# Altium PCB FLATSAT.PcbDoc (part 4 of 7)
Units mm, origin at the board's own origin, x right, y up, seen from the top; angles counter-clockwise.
Board outline 430 x 350 mm, 5 copper layers (Top Layer, Internal Plane 1, Internal Plane 2, DELETEME, Bottom Layer); 808 components, 852 nets, 6407 pads, 939 vias.
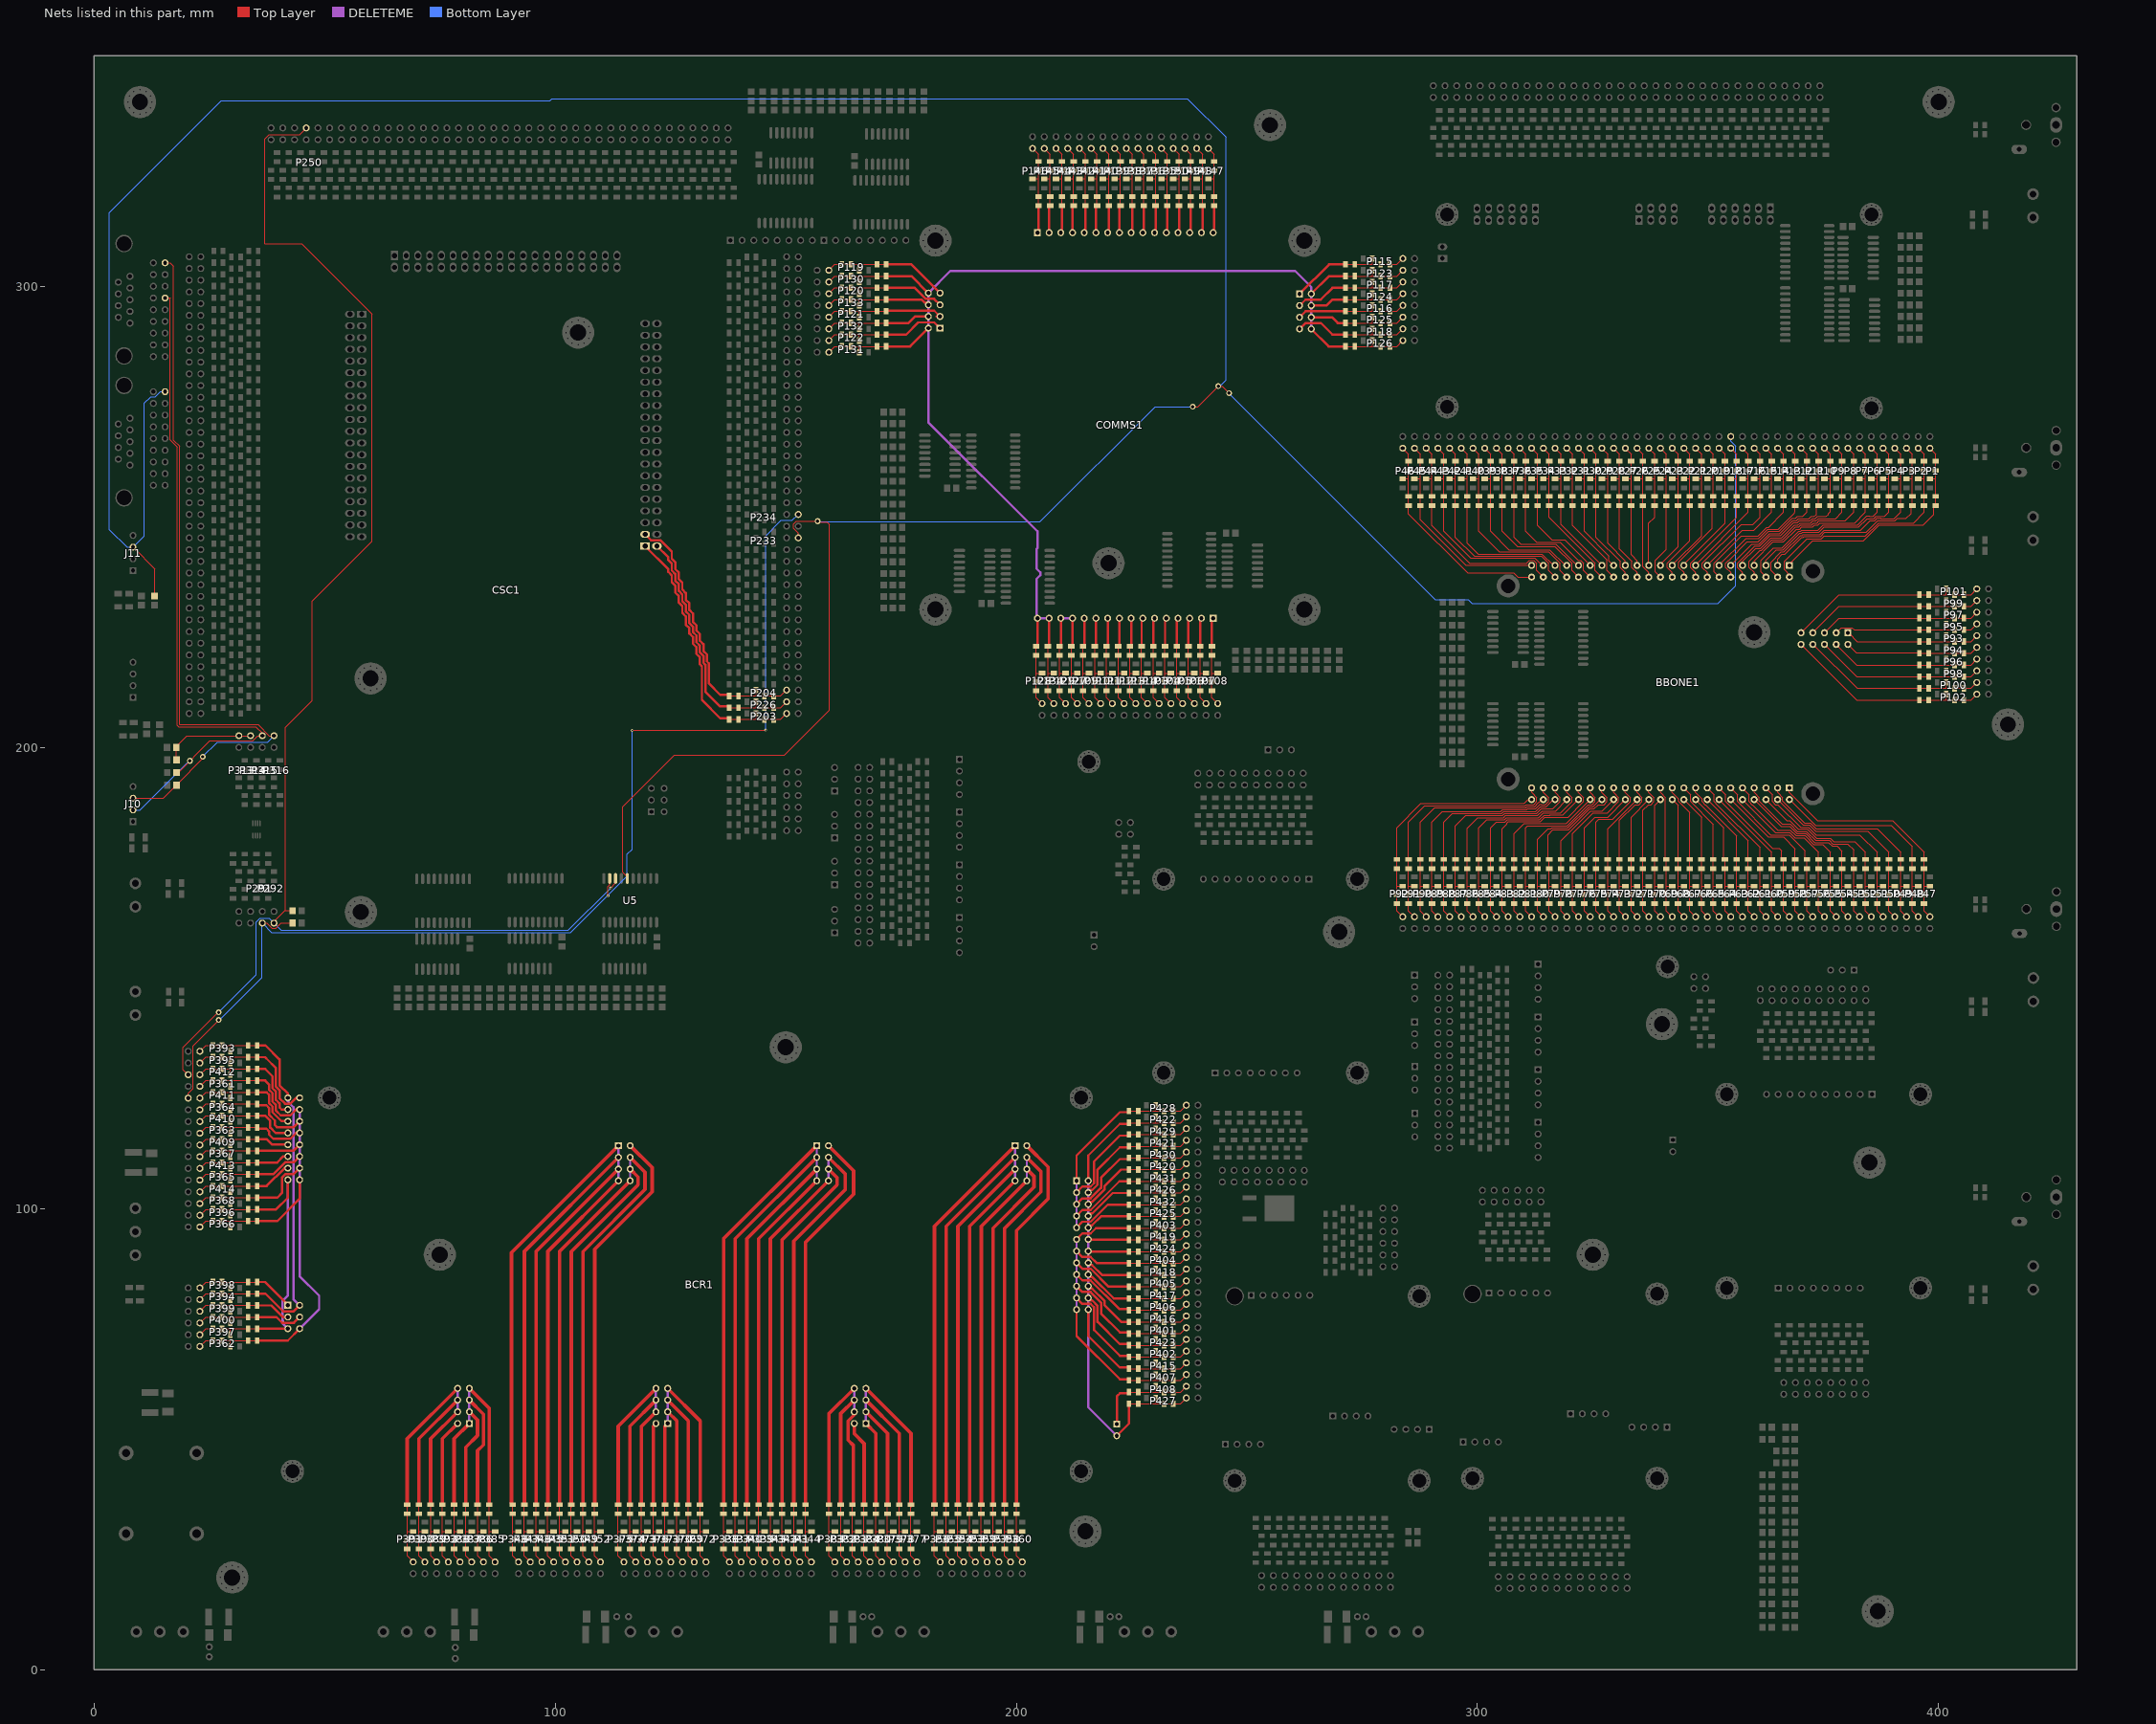
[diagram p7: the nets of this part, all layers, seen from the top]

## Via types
v1: diameter 1.016, hole 0.508, Top Layer to Bottom Layer, 541 vias
v2: diameter 0.6, hole 0.3, Top Layer to Bottom Layer, 214 vias
v3: diameter 1.27, hole 0.711, Top Layer to Bottom Layer, 147 vias
v4: diameter 0.8, hole 0.5, Top Layer to Bottom Layer, 31 vias
v5: diameter 0.5, hole 0.3, Top Layer to Bottom Layer, tented bottom, 5 vias
v6: diameter 1.27, hole 0.635, Top Layer to Bottom Layer, tented both sides, 1 vias

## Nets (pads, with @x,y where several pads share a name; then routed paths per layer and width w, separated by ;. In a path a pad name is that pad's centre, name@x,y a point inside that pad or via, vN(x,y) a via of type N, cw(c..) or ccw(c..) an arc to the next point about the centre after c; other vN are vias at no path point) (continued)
I2C1_SDA: J11.3 P18.1 P201.1 P233.1 R3.2 U5.6 | length 824.4
  Top Layer w0.152: U5.6@115.653,171.6 115.653,171.984 114.987,172.65 114.681,172.956 114.681,187.198 125.857,198.374 149.743,198.374 159.465,208.096 159.465,248.342 158.944,248.863 157.162,248.863 v3(156.925,249.1)
  Top Layer w0.254: J11.3@8.5,243.08 J11.3@8.5,243.46 13.233,238.727 R3.2@13.233,232.877 ; P233.1@152.734,245.474 152.734,246.522 151.679,247.577 151.679,248.451 152.328,249.1 v3(156.925,249.1) ; v3(238.252,273.914) 239.319,273.914 v3(243.789,278.384) 244.641,278.384 v3(246.15,276.875)
  Bottom Layer w0.254: P201.1@15.443,277.176 14.43,277.176 13.35,276.095 12.342,276.095 10.947,274.701 10.947,245.907 J11.3@8.5,243.46 7.163,243.46 3.404,247.219 3.404,316.027 27.661,340.284 98.874,340.284 99.313,340.723 237.077,340.723 245.44,332.359 245.44,279.679 244.145,278.384 v3(243.789,278.384) ; v3(156.925,249.1) 157.043,248.982 205.171,248.982 230.103,273.914 v3(238.252,273.914) ; v3(246.15,276.875) 245.9,277.125 245.8,277.125 290.82,232.105 298.001,232.105 298.855,231.25 352.164,231.25 356.01,235.096 356.01,265.34 354.918,266.433 P18.1@354.918,267.445
I2C2_SCL: P234.1 P291.1 P411.1 R8.2 U5.9 | length 254.4
  Top Layer w0.254: P411.1@20.451,123.96 20.451,124.973 21.531,126.053 21.531,135.323 26.935,140.727 26.935,141.224 27.051,141.108 27.247,141.108 v3(27.051,140.912) ; P291.1@36.519,161.92 37.532,161.92 38.612,160.84 39.507,160.84 40.591,161.925 R8.2@43.069,161.925 ; v2@111.435,167.869 111.435,169.796 111.917,170.278 111.917,171.526 U5.9@111.843,171.6 ; v2(111.481,167.869) v2@111.481,167.996 ; v2(116.713,203.708) 116.778,203.773 v2(145.669,203.773)
  Bottom Layer w0.254: v3(27.051,140.912) 27.247,141.108 27.443,141.108 36.42,150.085 P291.1@36.42,162.052 ; P291.1@36.519,161.92 38.547,159.893 103.378,159.893 112.074,168.589 115.646,172.161 115.646,176.84 116.713,177.907 v2(116.713,203.708) ; v2(145.669,203.773) 145.669,245.919 149,249.25 151.43,249.25 P234.1@152.734,250.554
I2C2_SCL_5V: J10.2 P191.1 P315.1 R10.2 | length 152
  Top Layer w0.254: P191.1@15.443,297.496 16.51,297.496 16.523,297.483 16.523,266.762 18.11,265.174 18.11,204.789 18.378,204.521 35.117,204.521 36.519,203.118 P315.1@36.519,202.56 35.507,202.56 34.427,201.48 25.188,201.48 R10.2@18.153,194.445
  Bottom Layer w0.254: J10.2@8.5,186.46 10.024,186.46 20.287,196.723 ; v3(20.812,197.104) v3@20.939,197.104
I2C2_SDA: P250.1 P292.1 P412.1 R7.2 U5.8 | length 329.6
  Top Layer w0.254: P412.1@20.451,129.04 19.371,130.121 19.371,135.009 26.826,142.465 26.935,142.465 v3(27.051,142.581) ; P292.1@39.059,161.92 39.059,162.3 41.529,164.77 41.529,204.35 47.371,210.192 47.371,231.775 60.325,244.729 60.325,293.99 45.07,309.245 37.084,309.245 37.084,332.012 37.987,332.914 44.594,332.914 P250.1@46.054,334.374 ; 41.368,164.592 R7.2@43.069,164.592 ; v2(112.039,169.545) 112.039,169.57 113.113,170.644 U5.8@113.113,171.6
  Bottom Layer w0.254: v3(27.051,142.581) 35.179,150.709 35.179,162.108 36.072,163.001 37.979,163.001 P292.1@39.059,161.92 40.579,160.401 102.87,160.401 v2@112.027,169.558 ; v2(112.039,169.545) v2@112.039,169.57
I2C2_SDA_5V: J10.3 P192.1 P316.1 R9.2 | length 159.8
  Top Layer w0.254: J10.3@8.5,189 15.075,189 R9.2@17.904,191.829 ; P192.1@15.443,305.116 16.51,305.116 17.272,304.354 17.272,266.659 18.567,265.364 18.567,204.978 35.629,204.978 38.047,202.56 P316.1@39.059,202.56 ; R9.2@17.562,192.187 18.187,192.187 v3@23.622,197.622
  Bottom Layer w0.254: v3(23.622,198) 26.79,201.168 37.667,201.168 P316.1@39.059,202.56
NetBBONE1_A01: BBONE1.A01 P1.2 | length 38.1
  Top Layer w0.254: BBONE1.A01@367.618,239.505 367.618,239.759 372.698,244.839 383.72,244.839 387.149,248.268 396.616,248.268 398.936,250.588 398.936,252.043 P1.2@399.368,252.475
NetBBONE1_A02: BBONE1.A02 P2.2 | length 40
  Top Layer w0.254: BBONE1.A02@367.618,236.965 367.618,237.514 366.526,238.606 366.526,240.404 371.418,245.296 374.599,245.296 375.157,245.855 384.09,245.855 386.96,248.725 394.534,248.725 396.828,251.02 P2.2@396.828,252.459
NetBBONE1_A03: BBONE1.A03 P3.2 | length 35.9
  Top Layer w0.254: BBONE1.A03@365.078,239.505 365.078,240.927 366.094,241.943 366.662,241.943 370.269,245.55 370.644,245.55 370.847,245.753 374.409,245.753 375.324,246.668 384.256,246.668 386.771,249.182 390.557,249.182 391.04,249.665 392.933,249.665 394.034,250.766 P3.2@394.034,252.221
NetBBONE1_A04: BBONE1.A04 P4.2 | length 37.9
  Top Layer w0.254: BBONE1.A04@365.078,236.965 363.63,238.413 363.63,240.034 363.554,240.11 365.845,242.401 366.473,242.401 370.08,246.007 370.454,246.007 370.657,246.211 374.22,246.211 375.134,247.125 383.087,247.125 385.144,249.182 386.124,249.182 386.607,249.665 387.376,249.665 387.401,249.64 390.368,249.64 391.748,251.02 P4.2@391.748,252.459
NetBBONE1_A05: BBONE1.A05 P5.2 | length 33.5
  Top Layer w0.254: BBONE1.A05@362.538,239.505 362.538,240.572 364.824,242.858 366.283,242.858 369.89,246.465 370.265,246.465 370.468,246.668 374.03,246.668 375.173,247.811 382.666,247.811 384.495,249.64 385.935,249.64 386.417,250.122 387.565,250.122 387.591,250.097 388.285,250.097 389.208,251.02 389.208,252.459 P5.2@389.208,252.475
NetBBONE1_A06: BBONE1.A06 P6.2 | length 35.2
  Top Layer w0.254: BBONE1.A06@362.538,236.965 361.446,238.057 361.446,240.597 364.164,243.315 366.094,243.315 369.701,246.922 370.075,246.922 370.279,247.125 373.841,247.125 374.984,248.268 382.477,248.268 384.449,250.24 384.908,250.24 385.051,250.097 385.745,250.097 386.668,251.02 P6.2@386.668,252.459
NetBBONE1_A07: BBONE1.A07 P7.2 | length 31
  Top Layer w0.254: BBONE1.A07@359.998,239.505 359.998,240.521 364.062,244.585 366.333,244.585 369.127,247.379 369.886,247.379 370.318,247.811 372.651,247.811 373.108,248.268 373.803,248.268 374.26,248.725 381.834,248.725 384.128,251.02 384.128,252.459 P7.2@384.128,252.475
NetBBONE1_A08: BBONE1.A08 P8.2 | length 32.4
  Top Layer w0.254: BBONE1.A08@359.998,236.965 359.998,237.96 358.906,239.053 358.906,240.343 361.319,242.756 361.587,242.756 363.873,245.042 366.143,245.042 368.937,247.836 369.697,247.836 370.128,248.268 372.462,248.268 372.919,248.725 373.613,248.725 374.071,249.182 379.751,249.182 381.588,251.02 P8.2@381.588,252.459
NetBBONE1_A09: BBONE1.A09 P9.2 | length 28.3
  Top Layer w0.254: BBONE1.A09@357.458,239.505 357.458,240.382 360.289,243.213 361.397,243.213 363.683,245.499 365.954,245.499 368.748,248.293 369.507,248.293 369.939,248.725 372.272,248.725 372.73,249.182 373.424,249.182 373.881,249.64 377.668,249.64 379.048,251.02 379.048,252.459 P9.2@379.048,252.475
NetBBONE1_A10: BBONE1.A10 P10.2 | length 29.6
  Top Layer w0.254: BBONE1.A10@357.458,236.965 357.458,237.96 356.366,239.053 356.366,239.957 357.006,240.597 357.026,240.597 360.1,243.671 361.208,243.671 363.494,245.957 365.765,245.957 368.559,248.751 369.318,248.751 369.75,249.182 372.083,249.182 372.54,249.64 373.235,249.64 373.692,250.097 375.585,250.097 376.076,250.588 376.076,250.757 376.508,251.189 P10.2@376.508,252.459
NetBBONE1_A11: BBONE1.A11 P11.2 | length 24.7
  Top Layer w0.254: BBONE1.A11@354.918,239.505 359.541,244.128 361.018,244.128 363.304,246.414 365.575,246.414 368.369,249.208 369.129,249.208 369.56,249.64 371.894,249.64 372.351,250.097 373.045,250.097 373.536,250.588 P11.2@373.536,252.043
NetBBONE1_A12: BBONE1.A12 P12.2 | length 27.1
  Top Layer w0.254: BBONE1.A12@354.918,236.965 354.918,237.96 353.826,239.053 353.826,239.957 354.466,240.597 354.486,240.597 358.474,244.585 360.829,244.585 363.115,246.871 365.386,246.871 368.18,249.665 368.939,249.665 369.371,250.097 370.505,250.097 371.428,251.02 P12.2@371.428,252.459
NetBBONE1_A13: BBONE1.A13 P13.2 | length 22.7
  Top Layer w0.254: BBONE1.A13@352.378,239.505 358.271,245.398 360.995,245.398 362.926,247.328 365.197,247.328 368.736,250.867 368.888,251.189 368.888,252.459 P13.2@368.888,252.475
NetBBONE1_A14: BBONE1.A14 P14.2 | length 24.5
  Top Layer w0.254: BBONE1.A14@352.378,236.965 351.286,238.057 351.286,239.957 351.926,240.597 351.946,240.597 357.204,245.855 360.806,245.855 362.736,247.785 363.114,247.785 366.348,251.02 P14.2@366.348,252.459
NetBBONE1_A15: BBONE1.A15 P15.2 | length 20.2
  Top Layer w0.254: BBONE1.A15@349.838,239.505 357.458,247.125 359.913,247.125 363.808,251.02 363.808,252.459 P15.2@363.808,252.475
NetBBONE1_A16: BBONE1.A16 P16.2 | length 22.6
  Top Layer w0.254: BBONE1.A16@349.838,236.965 349.838,237.96 348.746,239.053 348.746,239.957 357.183,248.395 359.744,248.395 361.268,249.919 P16.2@361.268,252.459
NetBBONE1_A17: BBONE1.A17 P17.2 | length 17.7
  Top Layer w0.254: BBONE1.A17@347.298,239.505 347.298,239.59 358.728,251.02 358.728,252.459 P17.2@358.728,252.475
NetBBONE1_A18: BBONE1.A18 P18.2 | length 20.1
  Top Layer w0.254: BBONE1.A18@347.298,236.965 347.298,237.96 346.206,239.053 346.206,239.957 346.846,240.597 346.866,240.597 356.188,249.919 P18.2@356.188,252.459
NetBBONE1_A19: BBONE1.A19 P19.2 | length 16.7
  Top Layer w0.254: BBONE1.A19@344.758,239.505 344.758,239.759 353.648,248.649 353.648,252.459 P19.2@353.648,252.475
NetBBONE1_A20: BBONE1.A20 P20.2 | length 18.7
  Top Layer w0.254: BBONE1.A20@344.758,236.965 344.758,237.96 343.666,239.053 343.666,240.306 350.854,247.494 P20.2@350.854,252.205
NetBBONE1_A21: BBONE1.A21 P21.2 | length 15.6
  Top Layer w0.254: BBONE1.A21@342.218,239.505 348.568,245.855 348.568,252.459 P21.2@348.568,252.475
NetBBONE1_A22: BBONE1.A22 P22.2 | length 18
  Top Layer w0.254: BBONE1.A22@342.218,236.965 342.218,237.96 341.126,239.053 341.126,239.957 341.766,240.597 341.786,240.597 346.028,244.839 P22.2@346.028,252.459
NetBBONE1_A23: BBONE1.A23 P23.2 | length 14.5
  Top Layer w0.254: BBONE1.A23@339.678,239.505 339.678,239.759 343.488,243.569 343.488,252.459 P23.2@343.488,252.475
NetBBONE1_A24: BBONE1.A24 P24.2 | length 16.9
  Top Layer w0.254: BBONE1.A24@339.678,236.965 338.586,238.057 338.586,240.597 340.948,242.959 P24.2@340.948,252.459
NetBBONE1_A25: BBONE1.A25 P25.2 | length 13.5
  Top Layer w0.254: BBONE1.A25@337.138,239.505 337.138,248.649 338.408,249.919 338.408,252.459 P25.2@338.408,252.475
NetBBONE1_A26: BBONE1.A26 P26.2 | length 16
  Top Layer w0.254: P26.2@335.868,252.459 335.868,239.23 337.138,237.96 BBONE1.A26@337.138,236.965
NetBBONE1_A27: BBONE1.A27 P27.2 | length 13.5
  Top Layer w0.254: P27.2@333.328,252.475 333.328,252.459 333.328,241.791 334.598,240.521 BBONE1.A27@334.598,239.505
NetBBONE1_A28: BBONE1.A28 P28.2 | length 17.1
  Top Layer w0.254: P28.2@330.788,252.459 330.788,243.061 333.506,240.343 333.506,239.053 334.598,237.96 BBONE1.A28@334.598,236.965
NetBBONE1_A29: BBONE1.A29 P29.2 | length 14.5
  Top Layer w0.254: P29.2@328.248,252.475 328.248,252.459 328.248,244.331 332.058,240.521 BBONE1.A29@332.058,239.505
NetBBONE1_A30: BBONE1.A30 P30.2 | length 18.1
  Top Layer w0.254: P30.2@325.708,252.459 325.708,245.601 330.966,240.343 330.966,239.053 332.058,237.96 BBONE1.A30@332.058,236.965
NetBBONE1_A31: BBONE1.A31 P31.2 | length 15.6
  Top Layer w0.254: P31.2@323.168,252.475 323.168,252.459 323.168,246.871 328.527,241.512 328.527,240.496 BBONE1.A31@329.518,239.505
NetBBONE1_A32: BBONE1.A32 P32.2 | length 19.2
  Top Layer w0.254: P32.2@320.628,252.459 320.628,248.141 328.07,240.699 328.07,238.413 BBONE1.A32@329.518,236.965
NetBBONE1_A33: BBONE1.A33 P33.2 | length 16.7
  Top Layer w0.254: P33.2@318.088,252.475 318.088,252.459 318.088,248.395 BBONE1.A33@326.978,239.505
NetBBONE1_A34: BBONE1.A34 P34.2 | length 20.2
  Top Layer w0.254: P34.2@315.548,252.459 315.548,249.94 325.53,239.957 325.53,238.413 BBONE1.A34@326.978,236.965
NetBBONE1_A35: BBONE1.A35 P35.2 | length 19.3
  Top Layer w0.254: P35.2@313.008,252.475 313.008,252.459 313.008,248.141 316.139,245.01 318.933,245.01 BBONE1.A35@324.438,239.505
NetBBONE1_A36: BBONE1.A36 P36.2 | length 24.6
  Top Layer w0.254: P36.2@310.468,252.459 310.468,246.871 312.786,244.553 317.866,244.553 321.822,240.597 322.35,240.597 322.99,239.957 322.99,238.413 BBONE1.A36@324.438,236.965
NetBBONE1_A37: BBONE1.A37 P37.2 | length 23.4
  Top Layer w0.254: P37.2@307.928,252.475 307.928,252.459 307.928,245.601 309.434,244.095 316.959,244.095 321.549,239.505 BBONE1.A37@321.898,239.505
NetBBONE1_A38: BBONE1.A38 P38.2 | length 27.1
  Top Layer w0.254: P38.2@305.388,252.459 305.388,246.871 308.621,243.638 316.769,243.638 320.45,239.957 320.45,238.413 BBONE1.A38@321.898,236.965
NetBBONE1_A39: BBONE1.A39 P39.2 | length 25.2
  Top Layer w0.254: P39.2@302.848,252.475 302.848,252.459 302.848,246.871 306.836,242.883 315.631,242.883 319.009,239.505 BBONE1.A39@319.358,239.505
NetBBONE1_A40: BBONE1.A40 P40.2 | length 29.6
  Top Layer w0.254: P40.2@300.308,252.459 300.308,246.871 304.753,242.426 315.442,242.426 317.91,239.957 317.91,238.413 BBONE1.A40@319.358,236.965
NetBBONE1_A41: BBONE1.A41 P41.2 | length 29.2
  Top Layer w0.254: P41.2@297.768,252.475 297.768,252.459 297.768,244.331 300.13,241.969 314.005,241.969 316.469,239.505 BBONE1.A41@316.818,239.505
NetBBONE1_A42: BBONE1.A42 P42.2 | length 32.9
  Top Layer w0.254: P42.2@295.228,252.459 295.228,245.601 299.317,241.512 313.816,241.512 315.37,239.957 315.37,238.413 BBONE1.A42@316.818,236.965
NetBBONE1_A43: BBONE1.A43 P43.2 | length 30.2
  Top Layer w0.254: P43.2@292.688,252.475 292.688,252.459 292.688,246.871 298.505,241.054 312.38,241.054 313.929,239.505 BBONE1.A43@314.278,239.505
NetBBONE1_A44: BBONE1.A44 P44.2 | length 34.5
  Top Layer w0.254: P44.2@290.148,252.459 290.148,248.141 298.327,239.962 310.651,239.962 311.286,240.597 312.19,240.597 312.83,239.957 312.83,238.413 BBONE1.A44@314.278,236.965
NetBBONE1_A45: BBONE1.A45 P45.2 | length 31.3
  Top Layer w0.254: P45.2@287.608,252.475 287.608,252.459 287.608,249.411 297.514,239.505 BBONE1.A45@311.738,239.505
NetBBONE1_A46: BBONE1.A46 P46.2 | length 34.1
  Top Layer w0.254: P46.2@285.068,252.459 285.068,250.681 297.859,237.89 307.83,237.89 308.756,236.965 BBONE1.A46@311.738,236.965
NetBBONE1_B01: BBONE1.B01 P47.2 | length 37.1
  Top Layer w0.254: BBONE1.B01@367.618,191.245 367.618,190.25 368.71,189.157 368.71,189.137 373.714,184.133 389.97,184.133 396.828,177.275 396.828,175.751 P47.2@396.828,175.735
NetBBONE1_B02: BBONE1.B02 P48.2 | length 33.7
  Top Layer w0.254: BBONE1.B02@367.618,188.705 367.711,188.705 373.299,183.117 389.716,183.117 394.288,178.545 394.288,175.751 P48.2@394.288,175.735
NetBBONE1_B03: BBONE1.B03 P49.2 | length 35
  Top Layer w0.254: BBONE1.B03@365.078,191.245 365.078,190.25 366.17,189.157 366.17,188.375 370.911,183.634 372.135,183.634 373.414,182.355 386.668,182.355 391.748,177.275 P49.2@391.748,175.751
NetBBONE1_B04: BBONE1.B04 P50.2 | length 30.4
  Top Layer w0.254: BBONE1.B04@365.078,188.705 370.606,183.177 371.945,183.177 373.275,181.847 384.636,181.847 389.208,177.275 389.208,175.751 P50.2@389.208,175.735
NetBBONE1_B05: BBONE1.B05 P51.2 | length 32.3
  Top Layer w0.254: BBONE1.B05@362.538,191.245 363.986,189.797 363.986,188.253 364.626,187.613 365.154,187.613 370.047,182.72 371.756,182.72 373.391,181.085 382.858,181.085 386.668,177.275 P51.2@386.668,175.751
NetBBONE1_B06: BBONE1.B06 P52.2 | length 27.9
  Top Layer w0.254: BBONE1.B06@362.538,188.705 367.11,184.133 367.718,184.133 369.588,182.263 371.567,182.263 373.506,180.323 376.508,180.323 377.27,179.561 381.842,179.561 384.128,177.275 384.128,175.751 P52.2@384.128,175.735
NetBBONE1_B07: BBONE1.B07 P53.2 | length 30.2
  Top Layer w0.254: BBONE1.B07@359.998,191.245 359.998,190.25 361.09,189.157 361.09,188.375 366.094,183.371 367.834,183.371 369.399,181.806 371.377,181.806 373.317,179.866 376.319,179.866 377.081,179.104 380.267,179.104 381.588,177.783 P53.2@381.588,175.751
NetBBONE1_B08: BBONE1.B08 P54.2 | length 25.5
  Top Layer w0.254: BBONE1.B08@359.998,188.705 365.84,182.863 367.695,182.863 369.21,181.348 371.188,181.348 373.128,179.409 376.129,179.409 376.891,178.647 377.93,178.647 379.048,177.529 379.048,175.751 P54.2@379.048,175.735
NetBBONE1_B09: BBONE1.B09 P55.2 | length 27.3
  Top Layer w0.254: BBONE1.B09@357.458,191.245 358.906,189.797 358.906,188.253 359.546,187.613 359.566,187.613 365.078,182.101 367.811,182.101 369.02,180.891 370.998,180.891 372.938,178.951 374.832,178.951 376.508,177.275 P55.2@376.508,175.751
NetBBONE1_B10: BBONE1.B10 P56.2 | length 22.8
  Top Layer w0.254: BBONE1.B10@357.458,188.705 364.57,181.593 367.672,181.593 368.831,180.434 370.809,180.434 373.968,177.275 373.968,175.751 P56.2@373.968,175.735
NetBBONE1_B11: BBONE1.B11 P57.2 | length 24.7
  Top Layer w0.254: BBONE1.B11@354.918,191.245 356.366,189.797 356.366,188.253 363.584,181.034 367.584,181.034 370.996,177.622 370.996,176.183 P57.2@371.428,175.751
NetBBONE1_B12: BBONE1.B12 P58.2 | length 20.7
  Top Layer w0.254: BBONE1.B12@354.918,188.705 363.046,180.577 366.348,180.577 368.888,178.037 368.888,175.751 P58.2@368.888,175.735
NetBBONE1_B13: BBONE1.B13 P59.2 | length 22.1
  Top Layer w0.254: BBONE1.B13@352.378,191.245 353.826,189.797 353.826,188.253 363.965,178.113 365.425,178.113 365.916,177.622 365.916,176.183 P59.2@366.348,175.751
NetBBONE1_B14: BBONE1.B14 P60.2 | length 17.7
  Top Layer w0.254: BBONE1.B14@352.378,188.705 363.808,177.275 363.808,175.751 P60.2@363.808,175.735
NetBBONE1_B15: BBONE1.B15 P61.2 | length 20.2
  Top Layer w0.254: BBONE1.B15@349.838,191.245 351.286,189.797 351.286,188.253 351.926,187.613 351.946,187.613 361.268,178.291 P61.2@361.268,175.751
NetBBONE1_B16: BBONE1.B16 P62.2 | length 16.7
  Top Layer w0.254: BBONE1.B16@349.838,188.705 358.728,179.815 358.728,175.751 P62.2@358.728,175.735
NetBBONE1_B17: BBONE1.B17 P63.2 | length 19.2
  Top Layer w0.254: BBONE1.B17@347.298,191.245 347.298,190.25 348.746,188.802 348.746,188.253 349.386,187.613 349.406,187.613 356.188,180.831 P63.2@356.188,175.751
NetBBONE1_B18: BBONE1.B18 P64.2 | length 15.6
  Top Layer w0.254: BBONE1.B18@347.298,188.705 353.394,182.609 353.394,175.989 P64.2@353.648,175.735
NetBBONE1_B19: BBONE1.B19 P65.2 | length 18.1
  Top Layer w0.254: BBONE1.B19@344.758,191.245 346.206,189.797 346.206,188.253 351.108,183.35 P65.2@351.108,175.751
NetBBONE1_B20: BBONE1.B20 P66.2 | length 14.5
  Top Layer w0.254: BBONE1.B20@344.758,188.705 348.568,184.895 348.568,175.751 P66.2@348.568,175.735
NetBBONE1_B21: BBONE1.B21 P67.2 | length 17.1
  Top Layer w0.254: BBONE1.B21@342.218,191.245 342.218,190.25 343.666,188.802 343.666,188.253 346.028,185.89 P67.2@346.028,175.751
NetBBONE1_B22: BBONE1.B22 P68.2 | length 13.5
  Top Layer w0.254: BBONE1.B22@342.218,188.705 342.98,187.943 343.488,187.435 343.488,175.751 P68.2@343.488,175.735
NetBBONE1_B23: BBONE1.B23 P69.2 | length 15.8
  Top Layer w0.254: BBONE1.B23@339.678,191.245 339.678,190.25 340.77,189.157 P69.2@340.77,175.929
NetBBONE1_B24: BBONE1.B24 P70.2 | length 13.5
  Top Layer w0.254: P70.2@338.408,175.735 338.408,175.751 338.408,187.435 BBONE1.B24@339.678,188.705
NetBBONE1_B25: BBONE1.B25 P71.2 | length 17.2
  Top Layer w0.254: P71.2@335.868,175.751 335.868,186.419 337.062,187.613 337.59,187.613 338.23,188.253 338.23,189.157 337.138,190.25 BBONE1.B25@337.138,191.245
NetBBONE1_B26: BBONE1.B26 P72.2 | length 14.5
  Top Layer w0.254: P72.2@333.328,175.735 333.328,175.751 333.328,184.895 BBONE1.B26@337.138,188.705
NetBBONE1_B27: BBONE1.B27 P73.2 | length 18.5
  Top Layer w0.254: P73.2@330.788,175.751 330.788,184.248 334.152,187.613 335.05,187.613 335.69,188.253 335.69,189.157 334.598,190.25 BBONE1.B27@334.598,191.245
NetBBONE1_B28: BBONE1.B28 P74.2 | length 15.6
  Top Layer w0.254: P74.2@328.248,175.735 328.248,175.751 328.248,182.355 BBONE1.B28@334.598,188.705
NetBBONE1_B29: BBONE1.B29 P75.2 | length 20.8
  Top Layer w0.254: P75.2@325.708,175.751 325.708,183.879 326.267,184.438 329.335,184.438 333.15,188.253 333.15,189.157 332.058,190.25 BBONE1.B29@332.058,191.245
NetBBONE1_B30: BBONE1.B30 P76.2 | length 18.3
  Top Layer w0.254: P76.2@323.168,175.735 323.168,175.751 323.168,182.609 325.454,184.895 328.248,184.895 BBONE1.B30@332.058,188.705
NetBBONE1_B31: BBONE1.B31 P77.2 | length 21.9
  Top Layer w0.254: P77.2@320.628,175.751 320.628,181.339 325.073,185.784 328.142,185.784 330.61,188.253 330.61,189.157 329.518,190.25 BBONE1.B31@329.518,191.245
NetBBONE1_B32: BBONE1.B32 P78.2 | length 19.2
  Top Layer w0.254: P78.2@318.088,175.735 318.088,175.751 318.088,179.769 324.561,186.241 327.054,186.241 BBONE1.B32@329.518,188.705
NetBBONE1_B33: BBONE1.B33 P79.2 | length 24.6
  Top Layer w0.254: P79.2@315.548,175.735 315.294,175.989 315.294,181.085 316.335,182.126 319.799,182.126 324.371,186.698 325.269,186.698 326.184,187.613 327.43,187.613 328.07,188.253 328.07,189.157 326.978,190.25 BBONE1.B33@326.978,191.245
NetBBONE1_B34: BBONE1.B34 P80.2 | length 21.9
  Top Layer w0.254: P80.2@313.008,175.735 313.008,175.751 313.008,180.069 315.294,182.355 315.917,182.355 316.146,182.584 319.61,182.584 324.182,187.156 325.08,187.156 325.987,188.063 325.987,188.07 325.994,188.07 326.629,188.705 BBONE1.B34@326.978,188.705
NetBBONE1_B35: BBONE1.B35 P81.2 | length 27.7
  Top Layer w0.254: P81.2@310.468,175.751 310.468,182.609 310.9,183.041 319.42,183.041 323.992,187.613 324.89,187.613 325.53,188.253 325.53,189.157 324.438,190.25 BBONE1.B35@324.438,191.245
NetBBONE1_B36: BBONE1.B36 P82.2 | length 25.2
  Top Layer w0.254: P82.2@307.928,175.735 307.928,175.751 307.928,181.339 310.087,183.498 319.231,183.498 BBONE1.B36@324.438,188.705
NetBBONE1_B37: BBONE1.B37 P83.2 | length 30.2
  Top Layer w0.254: P83.2@305.388,175.751 305.388,182.406 306.404,183.422 306.404,183.625 306.726,183.947 313.697,183.947 314.62,184.87 315.867,184.87 ; 315.892,184.895 319.633,184.895 322.99,188.253 322.99,189.157 321.898,190.25 BBONE1.B37@321.898,191.245
NetBBONE1_B38: BBONE1.B38 P84.2 | length 28.4
  Top Layer w0.254: P84.2@302.848,175.735 302.848,175.751 302.848,182.609 304.118,183.879 306.011,183.879 306.511,184.379 313.482,184.379 314.43,185.327 315.677,185.327 315.703,185.352 318.545,185.352 BBONE1.B38@321.898,188.705
NetBBONE1_B39: BBONE1.B39 P85.2 | length 32.8
  Top Layer w0.254: P85.2@300.308,175.751 300.308,182.609 302.035,184.336 305.822,184.336 306.296,184.81 313.267,184.81 314.241,185.784 315.488,185.784 315.513,185.809 318.007,185.809 320.45,188.253 320.45,189.157 319.358,190.25 BBONE1.B39@319.358,191.245
NetBBONE1_B40: BBONE1.B40 P86.2 | length 30.9
  Top Layer w0.254: P86.2@297.768,175.735 297.768,175.751 297.768,182.507 300.054,184.793 305.633,184.793 306.081,185.242 313.053,185.242 314.052,186.241 315.299,186.241 315.324,186.267 316.92,186.267 BBONE1.B40@319.358,188.705
NetBBONE1_B41: BBONE1.B41 P87.2 | length 35.5
  Top Layer w0.254: P87.2@295.228,175.735 295.228,175.751 295.228,182.965 297.514,185.251 305.443,185.251 305.867,185.674 312.838,185.674 313.862,186.698 315.109,186.698 315.135,186.724 316.381,186.724 317.91,188.253 317.91,189.157 316.818,190.25 BBONE1.B41@316.818,191.245
NetBBONE1_B42: BBONE1.B42 P88.2 | length 34.3
  Top Layer w0.254: P88.2@292.688,175.735 292.688,175.751 292.688,183.879 294.517,185.708 305.254,185.708 305.652,186.106 312.623,186.106 313.673,187.156 314.92,187.156 316.469,188.705 BBONE1.B42@316.818,188.705
NetBBONE1_B43: BBONE1.B43 P89.2 | length 38.6
  Top Layer w0.254: P89.2@290.148,175.735 290.148,175.751 290.148,183.879 292.434,186.165 305.065,186.165 305.437,186.538 310.671,186.538 310.831,186.698 312.569,186.698 313.509,187.638 313.8,187.638 313.826,187.613 314.73,187.613 315.37,188.253 315.37,189.157 314.278,190.25 BBONE1.B43@314.278,191.245
NetBBONE1_B44: BBONE1.B44 P90.2 | length 36.8
  Top Layer w0.254: P90.2@287.608,175.735 287.608,175.751 287.608,183.879 290.698,186.969 310.492,186.969 310.678,187.156 312.38,187.156 313.287,188.063 313.287,188.095 313.32,188.095 313.929,188.705 BBONE1.B44@314.278,188.705
NetBBONE1_B45: BBONE1.B45 P91.2 | length 41.2
  Top Layer w0.254: P91.2@285.068,175.735 285.068,175.751 285.068,183.879 288.59,187.401 310.313,187.401 310.524,187.613 312.19,187.613 312.83,188.253 312.83,189.157 311.738,190.25 BBONE1.B45@311.738,191.245
NetBBONE1_B46: BBONE1.B46 P92.2 | length 38.6
  Top Layer w0.254: P92.2@282.528,175.735 282.528,175.751 282.528,182.609 287.752,187.833 310.134,187.833 311.006,188.705 BBONE1.B46@311.738,188.705
NetBBONE1_P01: BBONE1.P01 P93.2 | length 16.3
  Top Layer w0.254: BBONE1.P01@380.318,224.9 380.445,224.9 382.35,222.995 P93.2@395.812,222.995
NetBBONE1_P02: BBONE1.P02 P94.2 | length 16.1
  Top Layer w0.254: BBONE1.P02@380.318,222.36 382.096,220.582 P94.2@395.685,220.582
NetBBONE1_P03: BBONE1.P03 P95.2 | length 18.7
  Top Layer w0.254: BBONE1.P03@377.778,224.9 378.87,225.992 381.217,225.992 381.674,225.535 P95.2@395.812,225.535
NetBBONE1_P04: BBONE1.P04 P96.2 | length 19.9
  Top Layer w0.254: BBONE1.P04@377.778,222.36 382.223,217.915 P96.2@395.812,217.915
NetBBONE1_P05: BBONE1.P05 P97.2 | length 21.9
  Top Layer w0.254: BBONE1.P05@375.238,224.9 378.413,228.075 P97.2@395.812,228.075
NetBBONE1_P06: BBONE1.P06 P98.2 | length 23.5
  Top Layer w0.254: BBONE1.P06@375.238,222.36 382.223,215.375 P98.2@395.812,215.375
NetBBONE1_P07: BBONE1.P07 P99.2 | length 25.5
  Top Layer w0.254: BBONE1.P07@372.698,224.9 378.413,230.615 P99.2@395.812,230.615
NetBBONE1_P08: BBONE1.P08 P100.2 | length 26.9
  Top Layer w0.254: BBONE1.P08@372.825,222.36 382.35,212.835 P100.2@395.812,212.835
NetBBONE1_P09: BBONE1.P09 P101.2 | length 29.1
  Top Layer w0.254: BBONE1.P09@370.158,224.9 378.413,233.155 P101.2@395.812,233.155
NetBBONE1_P10: BBONE1.P10 P102.2 | length 30.7
  Top Layer w0.254: BBONE1.P10@370.158,222.36 382.223,210.295 P102.2@395.812,210.295
NetBCR1_1: BCR1.1 P393.2 P394.2 | length 72.5
  Top Layer w0.508: P394.2@35.437,81.542 37.215,81.542 41.007,77.75 43.329,77.75 BCR1.1@44.611,79.032 ; P393.2@35.437,135.39 37.215,135.39 40.263,132.342 40.263,126.754 42.071,124.946 BCR1.1@42.071,124.032
  DELETEME w0.508: BCR1.1@42.071,124.032 42.071,123.2 43.278,121.992 43.278,80.365 BCR1.1@44.611,79.032
NetBCR1_2: BCR1.2 P395.2 | length 17.3
  Top Layer w0.508: P395.2@35.421,132.85 35.437,132.85 37.088,132.85 37.342,132.596 37.382,132.596 39.501,130.477 39.501,126.431 40.263,125.669 40.263,123.96 41.449,122.774 42.592,122.774 43.85,124.032 BCR1.2@44.611,124.032
NetBCR1_3: BCR1.3 P361.2 P362.2 P363.2 P364.2 P365.2 P366.2 P367.2 P368.2 | length 150.6
  Top Layer w0.508: P366.2@35.421,97.29 39.755,97.29 44.611,102.146 BCR1.3@44.611,106.252 ; P368.2@35.421,102.37 35.437,102.37 39.755,102.37 40.771,103.386 40.771,106.731 41.55,107.51 43.329,107.51 BCR1.3@44.611,108.792 ; P365.2@35.421,107.45 38.89,107.45 41.49,110.05 43.329,110.05 BCR1.3@44.611,111.332 ; P367.2@35.421,112.53 35.481,112.59 43.329,112.59 BCR1.3@44.611,113.872 ; P363.2@35.421,117.61 35.675,117.356 37.382,117.356 37.977,116.761 37.977,116.086 38.909,115.154 42.592,115.154 43.85,116.412 BCR1.3@44.611,116.412 ; P364.2@35.421,122.69 35.437,122.69 35.691,122.436 37.382,122.436 37.977,121.841 37.977,121 37.968,120.991 37.968,120.388 39.247,119.109 39.247,118.118 39.695,117.67 43.329,117.67 BCR1.3@44.611,118.952 ; P361.2@35.421,127.77 35.437,127.77 37.128,127.77 37.977,126.921 37.977,125.8 38.739,125.038 38.739,123.234 39.501,122.472 39.501,121.228 40.494,120.234 42.592,120.234 43.85,121.492 BCR1.3@44.611,121.492 ; P362.2@35.437,71.382 42.041,71.382 BCR1.3@44.611,73.952
  DELETEME w0.508: BCR1.3@44.611,73.952 48.848,78.19 48.848,81.12 44.611,85.357 BCR1.3@44.611,106.252 BCR1.3@44.611,108.792 BCR1.3@44.611,111.332 BCR1.3@44.611,113.872 BCR1.3@44.611,116.412 BCR1.3@44.611,118.952 BCR1.3@44.611,121.492
NetBCR1_4: BCR1.4 P396.2 P397.2 | length 51.5
  Top Layer w0.508: P397.2@35.421,73.922 35.451,73.952 BCR1.4@42.071,73.952 ; P396.2@35.437,99.83 39.501,99.83 42.071,102.4 BCR1.4@42.071,106.252
  DELETEME w0.508: BCR1.4@42.071,73.952 40.974,75.049 40.974,75.597 40.864,75.707 40.864,79.972 42.071,81.179 BCR1.4@42.071,106.252
NetBCR1_5: BCR1.5 P409.2 | length 7.1
  Top Layer w0.508: P409.2@35.437,115.07 37.469,115.07 38.667,113.872 BCR1.5@42.071,113.872
NetBCR1_6: BCR1.6 P410.2 | length 9
  Top Layer w0.508: P410.2@35.437,120.15 37.128,120.15 38.231,119.047 38.231,117.585 39.403,116.412 BCR1.6@42.071,116.412
NetBCR1_7: BCR1.7 P411.2 | length 11
  Top Layer w0.508: P411.2@35.437,125.23 37.469,125.23 37.977,124.722 37.977,122.919 38.739,122.157 38.739,120.912 40.699,118.952 BCR1.7@42.071,118.952
NetBCR1_8: BCR1.8 P412.2 | length 13.4
  Top Layer w0.508: P412.2@35.437,130.31 37.128,130.31 38.739,128.699 38.739,126.116 39.501,125.354 39.501,123.55 40.263,122.788 40.263,121.928 40.699,121.492 BCR1.8@42.071,121.492
NetBCR1_9: BCR1.9 P413.2 | length 7.2
  Top Layer w0.508: P413.2@35.421,109.99 35.437,109.99 39.755,109.99 41.097,111.332 BCR1.9@42.071,111.332
NetBCR1_10: BCR1.10 P414.2 | length 8.3
  Top Layer w0.508: P414.2@35.421,104.91 35.437,104.91 37.469,104.91 41.351,108.792 BCR1.10@42.071,108.792
NetBCR1_11: BCR1.11 P401.2 P402.2 P403.2 P404.2 P405.2 P406.2 P407.2 | length 125.7
  Top Layer w0.508: BCR1.11@213.071,78.092 213.071,72.398 222.468,63 224.175,63 P407.2@224.429,62.746 ; BCR1.11@213.071,80.632 214.353,79.35 216.132,79.35 216.869,78.613 216.869,73.68 222.468,68.08 224.175,68.08 P402.2@224.429,67.826 ; BCR1.11@213.071,83.172 213.095,83.172 214.353,81.914 216.108,81.914 218.393,79.629 218.393,77.236 222.468,73.16 224.175,73.16 P401.2@224.429,72.906 ; BCR1.11@213.071,85.712 213.095,85.712 214.353,84.454 216.108,84.454 222.322,78.24 224.175,78.24 P406.2@224.429,77.986 ; BCR1.11@213.071,88.252 214.353,86.97 216.132,86.97 220.036,83.066 224.413,83.066 P405.2@224.429,83.066 ; BCR1.11@213.071,90.792 214.353,89.51 216.132,89.51 217.496,88.146 224.413,88.146 P404.2@224.429,88.146 ; BCR1.11@213.071,93.332 214.353,94.614 216.132,94.614 217.284,95.766 224.413,95.766 P403.2@224.429,95.766
  DELETEME w0.508: BCR1.11@213.071,78.092 BCR1.11@213.071,80.632 BCR1.11@213.071,83.172 BCR1.11@213.071,85.712 BCR1.11@213.071,88.252 BCR1.11@213.071,90.792 BCR1.11@213.071,93.332
NetBCR1_12: BCR1.12 P408.2 | length 9
  Top Layer w0.508: BCR1.12@221.771,53.282 221.873,53.384 221.873,59.357 222.468,59.952 224.159,59.952 P408.2@224.413,60.206
NetBCR1_13: BCR1.13 P428.2 P429.2 P430.2 P431.2 P432.2 | length 95
  Top Layer w0.508: BCR1.13@213.071,95.872 214.353,97.154 216.132,97.154 219.824,100.846 P432.2@224.429,100.846 ; BCR1.13@213.071,98.412 214.353,99.694 216.132,99.694 222.364,105.926 224.413,105.926 P431.2@224.429,105.926 ; BCR1.13@213.071,100.952 213.095,100.952 214.353,102.21 216.108,102.21 218.393,104.495 218.393,106.677 222.468,110.752 224.175,110.752 P430.2@224.429,111.006 ; BCR1.13@213.071,103.492 214.353,104.774 216.132,104.774 216.869,105.511 216.869,110.233 222.468,115.832 224.175,115.832 P429.2@224.429,116.086 ; BCR1.13@213.071,106.032 213.071,111.515 222.468,120.912 224.175,120.912 P428.2@224.429,121.166
  DELETEME w0.508: BCR1.13@213.071,95.872 BCR1.13@213.071,98.412 BCR1.13@213.071,100.952 BCR1.13@213.071,103.492 BCR1.13@213.071,106.032
NetBCR1_14: BCR1.14 P415.2 P416.2 P417.2 P418.2 P419.2 P420.2 P421.2 P422.2 P423.2 P424.2 P425.2 P426.2 P427.2 | length 214.8
  Top Layer w0.508: BCR1.14@215.611,78.092 215.611,72.398 222.468,65.54 224.175,65.54 P415.2@224.429,65.286 ; BCR1.14@215.611,80.632 216.131,80.112 216.448,80.112 217.631,78.929 217.631,75.458 222.468,70.62 224.175,70.62 P423.2@224.429,70.366 ; BCR1.14@215.611,83.172 216.107,82.676 216.424,82.676 219.155,79.945 219.155,79.014 222.722,75.446 224.413,75.446 P416.2@224.429,75.446 ; BCR1.14@215.611,85.712 216.107,85.216 216.424,85.216 221.113,80.526 224.413,80.526 P417.2@224.429,80.526 ; BCR1.14@215.611,88.252 216.131,87.732 216.448,87.732 218.573,85.606 224.413,85.606 P418.2@224.429,85.606 ; BCR1.14@215.611,90.792 215.717,90.686 224.413,90.686 P424.2@224.429,90.686 ; BCR1.14@215.611,93.332 215.717,93.226 224.413,93.226 P419.2@224.429,93.226 ; BCR1.14@215.611,95.872 216.131,96.392 216.448,96.392 218.362,98.306 224.413,98.306 P425.2@224.429,98.306 ; BCR1.14@215.611,98.412 216.131,98.932 216.448,98.932 220.902,103.386 P426.2@224.429,103.386 ; BCR1.14@215.611,100.952 216.107,101.448 216.424,101.448 219.155,104.18 219.155,104.899 222.722,108.466 224.413,108.466 P420.2@224.429,108.466 ; BCR1.14@215.611,103.492 216.131,104.012 216.448,104.012 217.631,105.196 217.631,108.455 222.468,113.292 224.175,113.292 P421.2@224.429,113.546 ; BCR1.14@215.611,106.032 215.611,111.515 222.468,118.372 224.175,118.372 P422.2@224.429,118.626 ; BCR1.14@221.771,50.742 224.429,53.4 P427.2@224.429,57.666
  DELETEME w0.508: BCR1.14@215.611,106.032 BCR1.14@215.611,103.492 BCR1.14@215.611,100.952 BCR1.14@215.611,98.412 BCR1.14@215.611,95.872 BCR1.14@215.611,93.332 BCR1.14@215.611,90.792 BCR1.14@215.611,88.252 BCR1.14@215.611,85.712 BCR1.14@215.611,83.172 BCR1.14@215.611,80.632 BCR1.14@215.611,78.092 215.611,56.902 BCR1.14@221.771,50.742
NetBCR1_15: BCR1.15 P337.2 P338.2 P339.2 P340.2 | length 331
  Top Layer w0.762: P338.2@136.529,35.806 136.529,93.457 BCR1.15@156.737,113.665 ; P337.2@139.069,35.806 139.069,93.457 BCR1.15@156.737,111.125 ; P340.2@141.609,35.806 141.609,93.457 BCR1.15@156.737,108.585 ; P339.2@144.149,35.806 144.149,35.822 144.149,93.457 BCR1.15@156.737,106.045
  DELETEME w0.508: BCR1.15@156.737,106.045 BCR1.15@156.737,108.585 BCR1.15@156.737,111.125 BCR1.15@156.737,113.665
NetBCR1_16: BCR1.16 P341.2 P342.2 P343.2 | length 240.5
  Top Layer w0.762: P343.2@146.689,35.806 146.689,93.457 BCR1.16@159.277,106.045 ; P342.2@149.229,35.806 149.229,93.226 161.167,105.164 161.167,106.695 BCR1.16@159.277,108.585 ; P341.2@151.769,35.806 151.769,92.972 162.945,104.148 162.945,107.457 BCR1.16@159.277,111.125
  DELETEME w0.508: BCR1.16@159.277,106.045 BCR1.16@159.277,108.585 BCR1.16@159.277,111.125
NetBCR1_17: BCR1.17 P344.2 | length 84.4
  Top Layer w0.762: P344.2@154.309,35.806 154.309,92.718 164.723,103.132 164.723,108.219 BCR1.17@159.277,113.665
NetBCR1_18: BCR1.18 P345.2 P346.2 P347.2 P348.2 | length 335.5
  Top Layer w0.762: P348.2@90.555,36.076 90.555,90.483 BCR1.18@113.737,113.665 ; P347.2@93.349,35.822 93.349,90.737 BCR1.18@113.737,111.125 ; P346.2@95.889,35.822 95.889,90.737 BCR1.18@113.737,108.585 ; P345.2@98.429,35.568 98.429,90.737 BCR1.18@113.737,106.045
  DELETEME w0.508: BCR1.18@113.737,106.045 BCR1.18@113.737,108.585 BCR1.18@113.737,111.125 BCR1.18@113.737,113.665
NetBCR1_19: BCR1.19 P349.2 P350.2 P351.2 | length 243.6
  Top Layer w0.762: P351.2@100.969,35.822 100.969,90.737 BCR1.19@116.277,106.045 ; P350.2@103.509,35.568 103.509,90.686 117.987,105.164 117.987,106.875 BCR1.19@116.277,108.585 ; P349.2@106.049,35.822 106.049,90.686 119.511,104.148 119.511,107.891 BCR1.19@116.277,111.125
  DELETEME w0.508: BCR1.19@116.277,106.045 BCR1.19@116.277,108.585 BCR1.19@116.277,111.125
NetBCR1_20: BCR1.20 P352.2 | length 85
  Top Layer w0.762: P352.2@108.589,35.806 108.589,91.194 121.035,103.64 121.035,108.907 BCR1.20@116.277,113.665
NetBCR1_21: BCR1.21 P353.2 P354.2 P355.2 P356.2 | length 326.5
  Top Layer w0.762: P356.2@182.249,35.806 182.249,35.822 182.249,96.177 BCR1.21@199.737,113.665 ; P355.2@184.789,35.806 184.789,35.822 184.789,96.177 BCR1.21@199.737,111.125 ; P354.2@187.329,35.806 187.329,35.822 187.329,96.177 BCR1.21@199.737,108.585 ; P353.2@189.869,35.806 189.869,35.822 189.869,96.177 BCR1.21@199.737,106.045
  DELETEME w0.508: BCR1.21@199.737,106.045 BCR1.21@199.737,108.585 BCR1.21@199.737,111.125 BCR1.21@199.737,113.665
NetBCR1_22: BCR1.22 P357.2 P358.2 P359.2 | length 236.4
  Top Layer w0.762: P359.2@192.409,35.806 192.409,35.822 192.409,96.177 BCR1.22@202.277,106.045 ; P357.2@194.949,35.806 194.949,35.822 194.949,95.766 203.839,104.656 203.839,107.023 BCR1.22@202.277,108.585 ; P358.2@197.489,35.806 197.489,35.822 197.489,95.766 205.363,103.64 205.363,108.039 BCR1.22@202.277,111.125
  DELETEME w0.508: BCR1.22@202.277,106.045 BCR1.22@202.277,108.585 BCR1.22@202.277,111.125
NetBCR1_23: BCR1.23 P360.2 | length 82.6
  Top Layer w0.762: P360.2@200.029,35.806 200.029,95.258 206.887,102.116 206.887,109.055 BCR1.23@202.277,113.665
NetBCR1_24: BCR1.24 P369.2 P370.2 P371.2 P372.2 | length 99
  Top Layer w0.762: P371.2@123.829,35.822 123.829,52.823 BCR1.24@124.405,53.399 ; BCR1.24@124.405,55.939 126.369,53.975 P370.2@126.369,35.822 ; BCR1.24@124.405,58.479 128.909,53.975 P369.2@128.909,35.822 ; BCR1.24@124.405,61.019 131.449,53.975 P372.2@131.449,35.822
  DELETEME w0.508: BCR1.24@124.405,53.399 BCR1.24@124.405,55.939 BCR1.24@124.405,58.479 BCR1.24@124.405,61.019
NetBCR1_25: BCR1.25 P373.2 P374.2 P375.2 | length 80.1
  Top Layer w0.762: P375.2@113.669,35.822 113.669,52.823 BCR1.25@121.865,61.019 ; P374.2@116.209,35.822 116.209,52.823 BCR1.25@121.865,58.479 ; P373.2@118.749,35.822 118.749,52.823 BCR1.25@121.865,55.939
  DELETEME w0.508: BCR1.25@121.865,55.939 BCR1.25@121.865,58.479 BCR1.25@121.865,61.019
NetBCR1_26: BCR1.26 P376.2 | length 17.8
  Top Layer w0.762: P376.2@121.289,35.822 121.289,52.823 BCR1.26@121.865,53.399
NetBCR1_27: BCR1.27 P377.2 P378.2 P379.2 P380.2 | length 103.3
  Top Layer w0.762: BCR1.27@167.405,53.399 169.549,51.255 P380.2@169.549,35.822 ; BCR1.27@167.405,55.939 172.089,51.255 P379.2@172.089,35.822 ; BCR1.27@167.405,58.479 174.629,51.255 P378.2@174.629,35.822 ; BCR1.27@167.405,61.019 177.169,51.255 P377.2@177.169,35.568
  DELETEME w0.508: BCR1.27@167.405,53.399 BCR1.27@167.405,55.939 BCR1.27@167.405,58.479 BCR1.27@167.405,61.019
NetBCR1_28: BCR1.28 P381.2 P382.2 P383.2 | length 77.1
  Top Layer w0.762: P383.2@159.389,35.822 159.389,55.543 BCR1.28@164.865,61.019 ; P382.2@161.929,35.822 161.929,55.543 BCR1.28@164.865,58.479 ; P381.2@164.647,36.254 164.647,48.693 163.531,49.809 163.531,53.952 164.865,55.286 BCR1.28@164.865,55.939
  DELETEME w0.508: BCR1.28@164.865,55.939 BCR1.28@164.865,58.479 BCR1.28@164.865,61.019
NetBCR1_29: BCR1.29 P384.2 | length 18.5
  Top Layer w0.762: BCR1.29@164.865,53.399 164.865,51.174 167.009,49.03 P384.2@167.009,35.822
NetBCR1_30: BCR1.30 P385.2 P386.2 P387.2 P388.2 | length 99.9
  Top Layer w0.762: P388.2@78.109,35.822 78.109,50.103 BCR1.30@81.405,53.399 ; P387.2@80.649,35.822 80.649,48.268 83.189,50.808 83.189,54.155 BCR1.30@81.405,55.939 ; BCR1.30@81.405,58.479 84.459,55.425 84.459,48.776 83.189,47.506 P386.2@83.189,35.822 ; BCR1.30@81.405,61.019 85.729,56.695 P385.2@85.729,35.822
  DELETEME w0.508: BCR1.30@81.405,53.399 BCR1.30@81.405,55.939 BCR1.30@81.405,58.479 BCR1.30@81.405,61.019
NetBCR1_31: BCR1.31 P389.2 P390.2 P391.2 | length 83.7
  Top Layer w0.762: P391.2@67.949,35.568 67.949,50.103 BCR1.31@78.865,61.019 ; P390.2@70.489,35.822 70.489,50.103 BCR1.31@78.865,58.479 ; P389.2@73.029,35.822 73.029,50.103 BCR1.31@78.865,55.939
  DELETEME w0.508: BCR1.31@78.865,55.939 BCR1.31@78.865,58.479 BCR1.31@78.865,61.019
NetBCR1_32: BCR1.32 P392.2 | length 18.9
  Top Layer w0.762: P392.2@75.569,35.822 75.569,50.103 BCR1.32@78.865,53.399
NetBCR1_33: BCR1.33 P398.2 | length 8.8
  Top Layer w0.508: P398.2@35.421,84.082 35.437,84.082 37.128,84.082 42.071,79.139 BCR1.33@42.071,79.032
NetBCR1_34: BCR1.34 P399.2 | length 7.7
  Top Layer w0.508: P399.2@35.421,79.002 35.437,79.002 38.485,79.002 40.995,76.492 BCR1.34@42.071,76.492
NetBCR1_35: BCR1.35 P400.2 | length 10.2
  Top Layer w0.508: P400.2@35.437,76.462 39.585,76.462 40.813,75.234 43.353,75.234 BCR1.35@44.611,76.492
NetC1_2: C1.2 P313.1 P314.1 R11.2 | length 20.1
  Top Layer w0.254: C1.2@17.327,200.588 18.216,200.588 20.188,202.56 P313.1@31.439,202.56 P314.1@33.979,202.56 ; R11.2@17.875,197.358 C1.2@17.875,200.025
NetCOMMS1_AFSK1_M0: COMMS1.AFSK1_M0 P144.2 | length 5.9
  Top Layer w0.508: COMMS1.AFSK1_M0@209.665,311.657 209.892,311.885 209.892,317.482 P144.2@209.892,317.498
NetCOMMS1_AFSK1_M1: COMMS1.AFSK1_M1 P145.2 | length 6
  Top Layer w0.508: COMMS1.AFSK1_M1@207.125,311.657 207.125,317.27 P145.2@207.352,317.498 P145.2@207.352,317.482
NetCOMMS1_AFSK1_RXD: COMMS1.AFSK1_RXD P143.2 | length 6
  Top Layer w0.508: COMMS1.AFSK1_RXD@212.205,311.657 212.205,317.27 P143.2@212.432,317.498 P143.2@212.432,317.482
NetCOMMS1_AFSK1_TXD: COMMS1.AFSK1_TXD P146.2 | length 5.9
  Top Layer w0.508: COMMS1.AFSK1_TXD@204.585,311.657 204.812,311.885 204.812,317.482 P146.2@204.812,317.498
NetCOMMS1_AFSK2_M0: COMMS1.AFSK2_M0 P148.2 | length 5.9
  Top Layer w0.508: COMMS1.AFSK2_M0@240.145,311.657 240.372,311.885 240.372,317.482 P148.2@240.372,317.498
NetCOMMS1_AFSK2_M1: COMMS1.AFSK2_M1 P149.2 | length 5.9
  Top Layer w0.508: COMMS1.AFSK2_M1@237.605,311.657 237.832,311.885 237.832,317.482 P149.2@237.832,317.498
NetCOMMS1_AFSK2_RXD: COMMS1.AFSK2_RXD P147.2 | length 5.9
  Top Layer w0.508: COMMS1.AFSK2_RXD@242.685,311.657 242.912,311.885 242.912,317.482 P147.2@242.912,317.498
NetCOMMS1_AFSK2_TXD: COMMS1.AFSK2_TXD P150.2 | length 5.9
  Top Layer w0.508: COMMS1.AFSK2_TXD@235.065,311.657 235.292,311.885 235.292,317.482 P150.2@235.292,317.498
NetCOMMS1_DTMF1_ES: COMMS1.DTMF1_ES P108.2 | length 6.2
  Top Layer w0.508: P108.2@242.42,221.962 242.42,221.978 242.42,227.773 COMMS1.DTMF1_ES@242.685,228.037
NetCOMMS1_DTMF1_Q1: COMMS1.DTMF1_Q1 P103.2 | length 6.1
  Top Layer w0.508: P103.2@229.72,221.962 229.72,221.978 229.72,227.718 COMMS1.DTMF1_Q1@229.95,227.948
NetCOMMS1_DTMF1_Q2: COMMS1.DTMF1_Q2 P104.2 | length 6.2
  Top Layer w0.508: P104.2@232.26,221.962 232.26,221.978 232.26,227.773 COMMS1.DTMF1_Q2@232.525,228.037
NetCOMMS1_DTMF1_Q3: COMMS1.DTMF1_Q3 P105.2 | length 6.2
  Top Layer w0.508: P105.2@234.8,221.962 234.8,221.978 234.8,227.773 COMMS1.DTMF1_Q3@235.065,228.037
NetCOMMS1_DTMF1_Q4: COMMS1.DTMF1_Q4 P106.2 | length 6.2
  Top Layer w0.508: P106.2@237.34,221.962 237.34,221.978 237.34,227.773 COMMS1.DTMF1_Q4@237.605,228.037
NetCOMMS1_DTMF1_ST: COMMS1.DTMF1_ST P107.2 | length 6.2
  Top Layer w0.508: P107.2@239.88,221.962 239.88,221.978 239.88,227.773 COMMS1.DTMF1_ST@240.145,228.037
NetCOMMS1_DTMF2_ES: COMMS1.DTMF2_ES P114.2 | length 6.1
  Top Layer w0.508: P114.2@227.18,221.962 227.18,221.978 227.18,227.718 COMMS1.DTMF2_ES@227.41,227.948
NetCOMMS1_DTMF2_Q1: COMMS1.DTMF2_Q1 P109.2 | length 6.3
  Top Layer w0.508: P109.2@214.456,221.852 214.48,221.876 214.745,222.141 COMMS1.DTMF2_Q1@214.745,228.037
NetCOMMS1_DTMF2_Q2: COMMS1.DTMF2_Q2 P110.2 | length 6.3
  Top Layer w0.508: P110.2@216.996,221.852 217.02,221.876 217.285,222.141 COMMS1.DTMF2_Q2@217.285,228.037
NetCOMMS1_DTMF2_Q3: COMMS1.DTMF2_Q3 P111.2 | length 6.3
  Top Layer w0.508: P111.2@219.536,221.852 219.56,221.876 219.825,222.141 COMMS1.DTMF2_Q3@219.825,228.037
NetCOMMS1_DTMF2_Q4: COMMS1.DTMF2_Q4 P112.2 | length 6.3
  Top Layer w0.508: P112.2@222.076,221.852 222.1,221.876 222.365,222.141 COMMS1.DTMF2_Q4@222.365,228.037
NetCOMMS1_DTMF2_ST: COMMS1.DTMF2_ST P113.2 | length 6.3
  Top Layer w0.508: P113.2@224.616,221.852 224.64,221.876 224.905,222.141 COMMS1.DTMF2_ST@224.905,228.037
NetCOMMS1_GMSK_RX1: COMMS1.GMSK_RX1 P117.2 | length 11.6
  Top Layer w0.508: COMMS1.GMSK_RX1@261.425,295.848 262.707,297.13 265.994,297.13 268.566,299.702 271.376,299.702 P117.2@271.392,299.702
NetCOMMS1_GMSK_RX2: COMMS1.GMSK_RX2 P118.2 | length 11.6
  Top Layer w0.508: COMMS1.GMSK_RX2@261.425,290.768 262.739,292.082 263.411,292.082 263.444,292.05 266.059,292.05 268.566,289.542 271.376,289.542 P118.2@271.392,289.542
NetCOMMS1_GMSK_TX1: COMMS1.GMSK_TX1 P115.2 | length 12.6
  Top Layer w0.508: COMMS1.GMSK_TX1@261.425,298.388 267.819,304.782 P115.2@271.376,304.782
NetCOMMS1_GMSK_TX2: COMMS1.GMSK_TX2 P116.2 | length 10.5
  Top Layer w0.508: COMMS1.GMSK_TX2@261.425,293.308 262.707,294.59 271.36,294.59 P116.2@271.392,294.622
NetCOMMS1_GND: COMMS1.GND P123.2 P124.2 P125.2 P126.2 P128.2 P130.2 P131.2 P132.2 P133.2 P134.2 | length 266.1
  Top Layer w0.508: P131.2@171.792,287.002 171.808,287.002 176.999,287.002 COMMS1.GND@180.935,290.937 ; P132.2@171.792,292.082 171.808,292.082 176.618,292.082 178.014,293.477 COMMS1.GND@180.935,293.477 ; P133.2@171.792,297.162 171.808,297.162 179.473,297.162 180.098,296.537 180.415,296.537 COMMS1.GND@180.935,296.017 ; P130.2@171.792,302.242 171.808,302.242 177.25,302.242 COMMS1.GND@180.935,298.557 ; P128.2@204.55,221.852 204.585,221.887 COMMS1.GND@204.585,228.037 ; P134.2@206.836,222.106 207.125,222.395 COMMS1.GND@207.125,228.037 ; COMMS1.GND@263.965,290.768 267.73,287.002 P126.2@271.376,287.002 ; COMMS1.GND@263.965,293.308 268.46,293.308 269.686,292.082 P125.2@271.376,292.082 ; COMMS1.GND@263.965,295.848 267.252,295.848 268.566,297.162 271.376,297.162 P124.2@271.392,297.162 ; COMMS1.GND@263.965,298.388 267.819,302.242 271.376,302.242 P123.2@271.392,302.242
  DELETEME w0.508: COMMS1.GND@207.125,228.037 COMMS1.GND@204.585,228.037 204.418,228.204 204.418,236.583 205.207,237.372 205.207,237.978 204.418,238.767 204.418,243.078 204.585,243.245 204.585,246.9 180.935,270.55 COMMS1.GND@180.935,290.937 COMMS1.GND@180.935,293.477 COMMS1.GND@180.935,296.017 COMMS1.GND@180.935,298.557 185.747,303.37 260.43,303.37 263.965,299.835 COMMS1.GND@263.965,298.388 COMMS1.GND@263.965,295.848 COMMS1.GND@263.965,293.308 COMMS1.GND@263.965,290.768
NetCOMMS1_RX1: COMMS1.RX1 P121.2 | length 13
  Top Layer w0.508: P121.2@171.792,294.622 171.906,294.735 182.217,294.735 COMMS1.RX1@183.475,293.477 182.714,293.477
NetCOMMS1_RX2: COMMS1.RX2 P122.2 | length 13.3
  Top Layer w0.508: P122.2@171.792,289.542 171.808,289.542 176.11,289.542 178.764,292.195 182.217,292.195 COMMS1.RX2@183.475,290.937
NetCOMMS1_S0: COMMS1.S0 P135.2 | length 5.9
  Top Layer w0.508: COMMS1.S0@232.525,311.657 232.752,311.885 232.752,317.482 P135.2@232.752,317.498
NetCOMMS1_S1: COMMS1.S1 P136.2 | length 5.9
  Top Layer w0.508: COMMS1.S1@229.985,311.657 230.212,311.885 230.212,317.482 P136.2@230.212,317.498
NetCOMMS1_S2: COMMS1.S2 P137.2 | length 5.9
  Top Layer w0.508: COMMS1.S2@227.445,311.657 227.672,311.885 227.672,317.482 P137.2@227.672,317.498
NetCOMMS1_S3: COMMS1.S3 P138.2 | length 5.9
  Top Layer w0.508: COMMS1.S3@224.905,311.657 225.132,311.885 225.132,317.482 P138.2@225.132,317.498
NetCOMMS1_S4: COMMS1.S4 P139.2 | length 6
  Top Layer w0.508: COMMS1.S4@222.365,311.657 222.365,317.27 P139.2@222.592,317.498 P139.2@222.592,317.482
NetCOMMS1_S5: COMMS1.S5 P140.2 | length 5.9
  Top Layer w0.508: COMMS1.S5@219.825,311.657 220.052,311.885 220.052,317.482 P140.2@220.052,317.498
NetCOMMS1_S6: COMMS1.S6 P141.2 | length 6
  Top Layer w0.508: COMMS1.S6@217.285,311.657 217.285,317.27 P141.2@217.512,317.498 P141.2@217.512,317.482
NetCOMMS1_S7: COMMS1.S7 P142.2 | length 5.9
  Top Layer w0.508: COMMS1.S7@214.745,311.657 214.972,311.885 214.972,317.482 P142.2@214.972,317.498
NetCOMMS1_TX1: COMMS1.TX1 P119.2 | length 14.3
  Top Layer w0.508: P119.2@171.792,304.782 171.808,304.782 177.25,304.782 COMMS1.TX1@183.475,298.557
NetCOMMS1_TX2: COMMS1.TX2 P120.2 | length 13.2
  Top Layer w0.508: P120.2@171.792,299.702 171.808,299.702 178.011,299.702 180.414,297.299 182.193,297.299 COMMS1.TX2@183.475,296.017
NetCOMMS1_VCC: COMMS1.VCC P127.2 P129.2 | length 15.2
  Top Layer w0.508: P129.2@209.665,221.633 COMMS1.VCC@209.665,228.037 ; P127.2@211.916,221.852 211.94,221.876 212.205,222.141 COMMS1.VCC@212.205,228.037
  DELETEME w0.508: COMMS1.VCC@209.665,228.037 COMMS1.VCC@212.205,228.037
NetCSC1_C1_1: CSC1.C1_1 P203.2 | length 46.1
  Top Layer w0.508: CSC1.C1_1@119.532,243.692 124.54,238.684 124.54,238.094 125.302,237.332 125.302,235.87 126.064,235.108 126.064,233.646 126.826,232.884 126.826,231.421 127.588,230.659 127.588,229.197 128.35,228.435 128.35,226.638 129.112,225.876 129.112,224.748 129.874,223.986 129.874,222.524 130.636,221.762 130.636,220.299 131.398,219.537 131.398,218.075 131.842,217.631 131.842,210.319 135.803,206.358 137.51,206.358 P203.2@137.764,206.104
NetCSC1_C1_2: CSC1.C1_2 P226.2 | length 42.5
  Top Layer w0.508: CSC1.C1_2@122.072,243.692 124.54,241.224 124.54,240.634 125.302,239.872 125.302,238.41 126.064,237.648 126.064,236.186 126.826,235.424 126.826,233.961 127.588,233.199 127.588,231.737 128.35,230.975 128.35,229.512 129.112,228.75 129.112,226.954 129.874,226.192 129.874,225.064 130.636,224.302 130.636,222.839 131.398,222.077 131.398,220.615 132.16,219.853 132.16,218.391 132.604,217.946 132.604,212.097 135.803,208.898 137.51,208.898 P226.2@137.764,208.644
NetCSC1_C1_3: CSC1.C1_3 P204.2 | length 44.8
  Top Layer w0.508: CSC1.C1_3@119.532,246.232 120.798,244.966 122.851,244.966 125.302,242.515 125.302,240.95 126.064,240.188 126.064,238.726 126.826,237.964 126.826,236.501 127.588,235.739 127.588,234.277 128.35,233.515 128.35,232.052 129.112,231.29 129.112,229.828 129.874,229.066 129.874,227.27 130.636,226.508 130.636,225.379 131.398,224.617 131.398,223.155 132.16,222.393 132.16,220.931 132.922,220.169 132.922,218.706 133.366,218.262 133.366,213.875 135.803,211.438 137.51,211.438 P204.2@137.764,211.184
